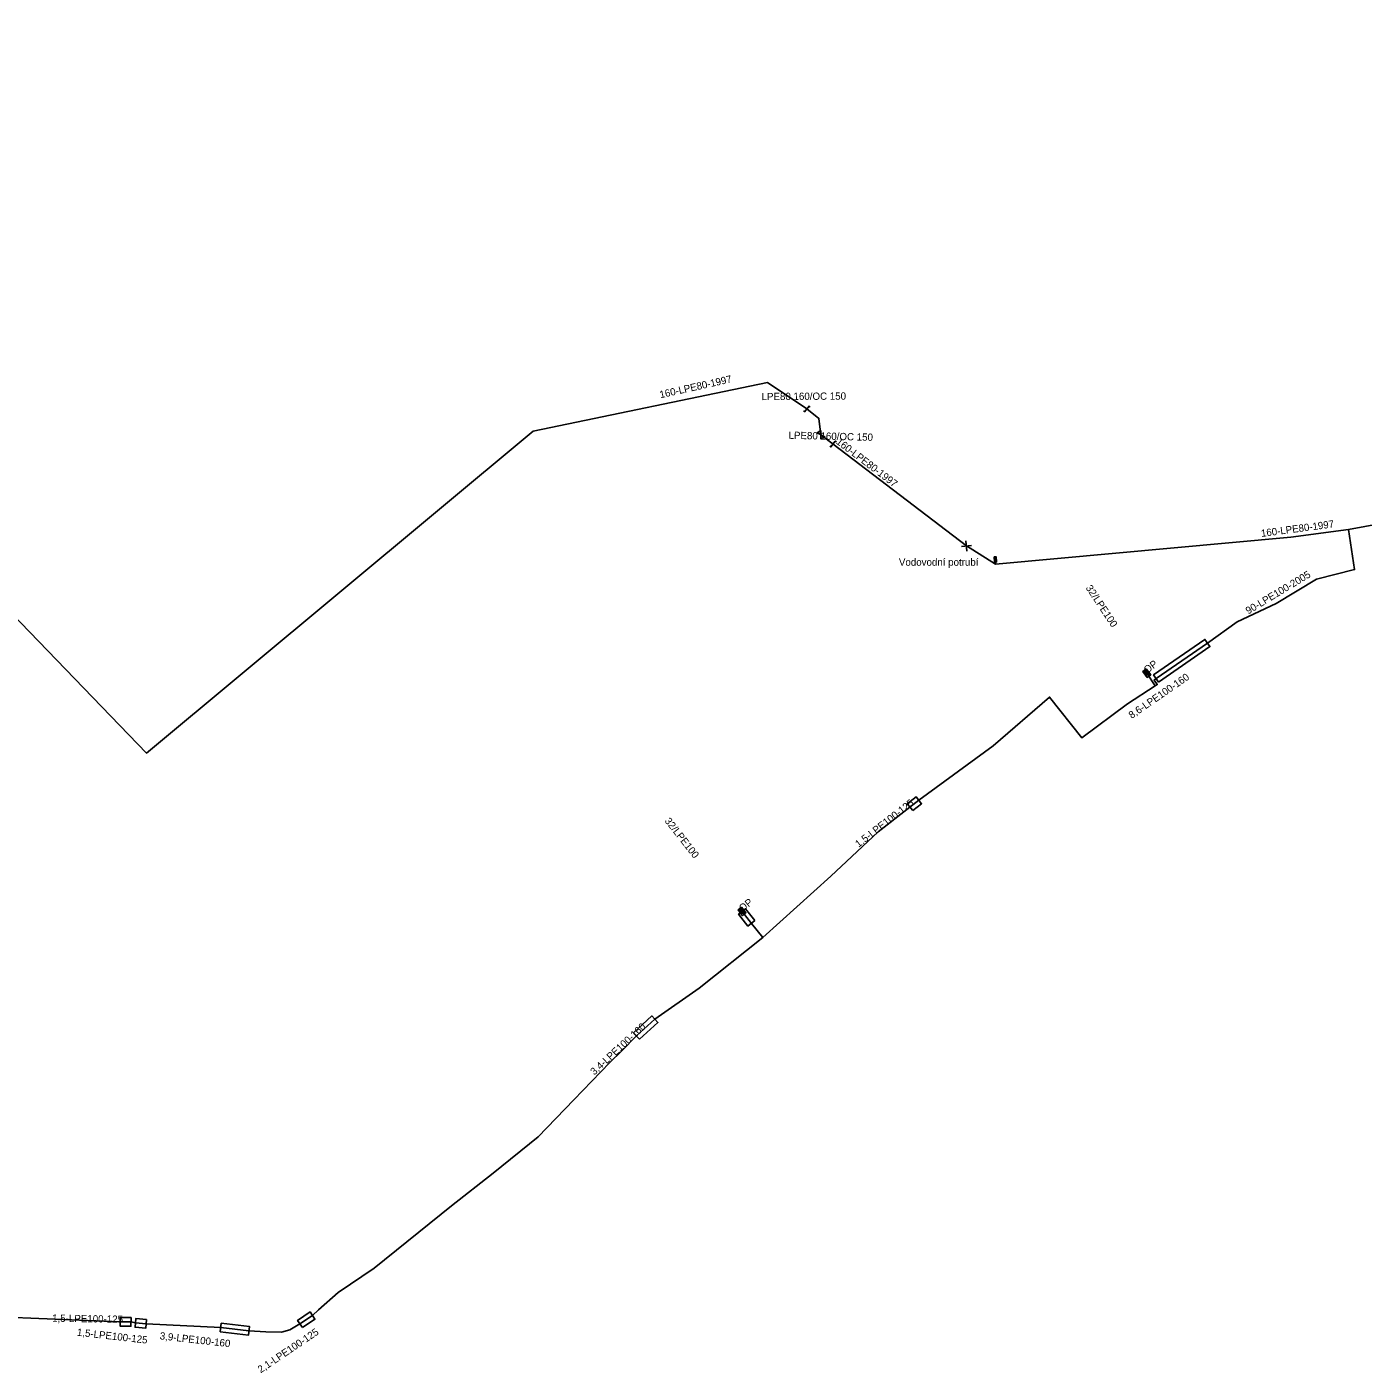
# Model space of a CAD drawing. Extents: x -762509 to -761250, y -1153000 to -1152256.
# Drawn here: x -762336.3 to -762152.8, y -1152944.2 to -1152759.4 of the extents above; entities that cross this region are included whole.
import ezdxf

# ---------------------------------------------------------------- set-up
doc = ezdxf.new("R2010")
doc.units = 0
for name, color, linetype in [('Vrstva 10', 7, 'Continuous'), ('Vrstva 21', 7, 'Continuous'), ('Vrstva 22', 7, 'Continuous'), ('Vrstva 24', 7, 'Continuous'), ('Vrstva 25', 7, 'Continuous'), ('Vrstva 29', 7, 'Continuous'), ('Vrstva 31', 7, 'Continuous'), ('Vrstva 32', 7, 'Continuous')]:
    doc.layers.add(name, color=color, linetype=linetype)

msp = doc.modelspace()

# ---------------------------------------------------------------- linework, layer by layer
at = {"layer": 'Vrstva 10'}
for p, q in [((-762207.964, -1152830.702), (-762206.557, -1152830.559)), ((-762207.189, -1152831.334), (-762207.332, -1152829.927))]:
    msp.add_line(p, q, dxfattribs=at)
at = {"layer": 'Vrstva 21'}
for points in [[(-762229.19, -1152811.83), (-762234.58, -1152808.18), (-762266.76, -1152814.86), (-762319.87, -1152859.08), (-762360.62, -1152816.89), (-762355.03, -1152811.99), (-762364.5, -1152800.75), (-762359.08, -1152772.07), (-762368.47, -1152760.2), (-762370.01, -1152761.74), (-762371.98, -1152759.36)], [(-762227.25, -1152815.36), (-762227.53, -1152813.12), (-762229.19, -1152811.83)], [(-762043.6, -1152833.45), (-762063.92, -1152811.87), (-762067.25, -1152812.52), (-762087.05, -1152815.27), (-762094.82, -1152816.92), (-762113.88, -1152820.87), (-762154.79, -1152828.37)], [(-762225.59, -1152816.64), (-762227.25, -1152815.36)], [(-762154.79, -1152828.37), (-762162.71, -1152829.42), (-762203.27, -1152833.15), (-762207.26, -1152830.63), (-762225.59, -1152816.64)], [(-762254.61, -1152899.97), (-762252.57, -1152897.94), (-762250.06, -1152895.63), (-762243.97, -1152891.38), (-762235.23, -1152884.43), (-762225.91, -1152876.01), (-762219.4, -1152869.9), (-762215.02, -1152866.52), (-762213.8, -1152865.57), (-762203.61, -1152858.08), (-762195.85, -1152851.4), (-762191.43, -1152856.97), (-762185.16, -1152852.33), (-762181.35, -1152849.84), (-762181.05, -1152849.69), (-762181.49, -1152849.07), (-762181.22, -1152848.85), (-762174.17, -1152843.97), (-762170.09, -1152841.05), (-762164.74, -1152838.54), (-762159.19, -1152835.19), (-762153.96, -1152833.88), (-762154.79, -1152828.37)], [(-762303.5, -1152938.57), (-762301.37, -1152938.63), (-762300.22, -1152938.31), (-762298.81, -1152937.49), (-762297.09, -1152936.33), (-762296.25, -1152935.55), (-762293.55, -1152933.16), (-762288.61, -1152929.82), (-762277.99, -1152921.28), (-762272.26, -1152916.76), (-762266.07, -1152911.77), (-762261.21, -1152906.72), (-762256.26, -1152901.6), (-762254.61, -1152899.97)], [(-762367.09, -1152935.51), (-762362.63, -1152935.58), (-762356.49, -1152935.86), (-762341.39, -1152936.46), (-762323.51, -1152937.19), (-762322.03, -1152937.21), (-762321.41, -1152937.33), (-762319.93, -1152937.48), (-762309.7, -1152937.99), (-762305.82, -1152938.43), (-762303.5, -1152938.57)]]:
    msp.add_lwpolyline(points, dxfattribs=at)
at = {"layer": 'Vrstva 22'}
msp.add_lwpolyline([(-762227.248, -1152814.777), (-762227.253, -1152815.943), (-762226.737, -1152815.637), (-762227.764, -1152815.083), (-762227.248, -1152814.777)], dxfattribs=at)
at = {"layer": 'Vrstva 24'}
msp.add_line((-762203.31, -1152832.151), (-762203.27, -1152833.15), dxfattribs=at)
msp.add_lwpolyline([(-762203.46, -1152832.157), (-762203.16, -1152832.145), (-762203.132, -1152832.844), (-762203.432, -1152832.856), (-762203.46, -1152832.157)], dxfattribs=at)
at = {"layer": 'Vrstva 25'}
for points in [[(-762229.659, -1152812.095), (-762229.503, -1152812.22), (-762228.877, -1152811.44), (-762228.721, -1152811.565)], [(-762226.051, -1152816.919), (-762225.891, -1152817.04), (-762225.289, -1152816.241), (-762225.129, -1152816.361)]]:
    msp.add_lwpolyline(points, dxfattribs=at)
at = {"layer": 'Vrstva 29'}
for points in [[(-762180.88, -1152849.34), (-762173.83, -1152844.46), (-762174.51, -1152843.48), (-762181.56, -1152848.36)], [(-762214.65, -1152866.99), (-762213.43, -1152866.04), (-762214.17, -1152865.1), (-762215.39, -1152866.05)], [(-762236.34, -1152882.1), (-762237.62, -1152880.47), (-762238.56, -1152881.21), (-762237.28, -1152882.84)], [(-762252.16, -1152898.38), (-762249.65, -1152896.07), (-762250.47, -1152895.19), (-762252.98, -1152897.5)], [(-762298.47, -1152937.99), (-762296.75, -1152936.83), (-762297.43, -1152935.83), (-762299.15, -1152936.99)], [(-762322.02, -1152936.61), (-762323.5, -1152936.59), (-762323.52, -1152937.79), (-762322.04, -1152937.81)], [(-762319.87, -1152936.88), (-762321.35, -1152936.73), (-762321.47, -1152937.93), (-762319.99, -1152938.08)], [(-762309.77, -1152938.59), (-762305.89, -1152939.03), (-762305.75, -1152937.83), (-762309.63, -1152937.39)]]:
    msp.add_lwpolyline(points, close=True, dxfattribs=at)
at = {"layer": 'Vrstva 31'}
for points in [[(-762181.35, -1152849.84), (-762182.5, -1152848.11)], [(-762235.23, -1152884.43), (-762236.81, -1152882.47), (-762238.09, -1152880.84)]]:
    msp.add_lwpolyline(points, dxfattribs=at)
at = {"layer": 'Vrstva 32'}
for p, q in [((-762182.603, -1152847.686), (-762182.882, -1152847.898)), ((-762182.76, -1152848.058), (-762182.481, -1152847.846)), ((-762182.734, -1152847.786), (-762182.613, -1152847.946)), ((-762182.518, -1152848.375), (-762182.239, -1152848.163)), ((-762238.199, -1152880.418), (-762238.474, -1152880.634)), ((-762238.35, -1152880.792), (-762238.075, -1152880.576)), ((-762238.329, -1152880.52), (-762238.205, -1152880.678)), ((-762238.104, -1152881.106), (-762237.828, -1152880.89))]:
    msp.add_line(p, q, dxfattribs=at)
for points in [[(-762182.564, -1152847.53), (-762181.958, -1152848.326), (-762182.435, -1152848.689), (-762183.042, -1152847.894), (-762182.564, -1152847.53)], [(-762182.421, -1152847.924), (-762182.621, -1152848.076), (-762182.651, -1152848.117), (-762182.659, -1152848.162), (-762182.647, -1152848.206), (-762182.629, -1152848.229), (-762182.59, -1152848.252), (-762182.547, -1152848.255), (-762182.499, -1152848.236), (-762182.299, -1152848.084)], [(-762182.239, -1152848.163), (-762182.161, -1152848.266), (-762182.149, -1152848.31), (-762182.152, -1152848.332), (-762182.17, -1152848.363), (-762182.21, -1152848.393), (-762182.245, -1152848.402), (-762182.266, -1152848.4), (-762182.305, -1152848.377), (-762182.384, -1152848.273)], [(-762238.162, -1152880.262), (-762237.545, -1152881.048), (-762238.017, -1152881.419), (-762238.634, -1152880.632), (-762238.162, -1152880.262)], [(-762238.014, -1152880.654), (-762238.211, -1152880.809), (-762238.241, -1152880.85), (-762238.248, -1152880.895), (-762238.235, -1152880.938), (-762238.217, -1152880.961), (-762238.178, -1152880.983), (-762238.134, -1152880.986), (-762238.087, -1152880.967), (-762237.889, -1152880.812)], [(-762237.828, -1152880.89), (-762237.748, -1152880.992), (-762237.735, -1152881.035), (-762237.739, -1152881.057), (-762237.756, -1152881.088), (-762237.795, -1152881.119), (-762237.83, -1152881.129), (-762237.852, -1152881.127), (-762237.891, -1152881.104), (-762237.971, -1152881.002)]]:
    msp.add_lwpolyline(points, dxfattribs=at)

# ---------------------------------------------------------------- texts
at = {"layer": 'Vrstva 10'}
msp.add_text('Vodovodní potrubí', height=1, dxfattribs=at).set_placement((-762216.54, -1152833.36))
at = {"layer": 'Vrstva 21'}
for s, rotation, p in [('160-LPE80-1997', 12.57108, (-762249.3, -1152810.36)), ('160-LPE80-1997', 322.64805, (-762225.25, -1152816.51)), ('160-LPE80-1997', 7.55209, (-762166.74, -1152829.41)), ('90-LPE100-2005', 31.11533, (-762168.54, -1152840.06))]:
    msp.add_text(s, height=1, rotation=rotation, dxfattribs=at).set_placement(p)
at = {"layer": 'Vrstva 25'}
for rotation, p in [(0.36011, (-762235.4, -1152810.62)), (358.54173, (-762231.71, -1152815.92))]:
    msp.add_text('LPE80 160/OC 150', height=1, rotation=rotation, dxfattribs=at).set_placement(p)
at = {"layer": 'Vrstva 29'}
for s, rotation, p in [('8,6-LPE100-160', 34.69093, (-762184.56, -1152854.41)), ('1,5-LPE100-125', 37.90748, (-762222.08, -1152872.1)), ('3,4-LPE100-160', 42.62394, (-762258.38, -1152903.38)), ('1,5-LPE100-125', 359.03823, (-762332.86, -1152937.18)), ('1,5-LPE100-125', 353.50542, (-762329.49, -1152939.09)), ('2,1-LPE100-125', 33.99646, (-762304.2, -1152944.27)), ('3,9-LPE100-160', 353.53018, (-762318.11, -1152939.59))]:
    msp.add_text(s, height=1, rotation=rotation, dxfattribs=at).set_placement(p)
at = {"layer": 'Vrstva 31'}
for rotation, p in [(303.61357, (-762190.93, -1152836.4)), (303.61357, (-762190.93, -1152836.4)), (308.1417, (-762248.78, -1152868.43)), (308.1417, (-762248.78, -1152868.43))]:
    msp.add_text('32/LPE100', height=1, rotation=rotation, dxfattribs=at).set_placement(p)
at = {"layer": 'Vrstva 32'}
for rotation, p in [(37.31075, (-762182.44, -1152848.2)), (37.31075, (-762182.44, -1152848.2)), (38.1417, (-762238.03, -1152880.94)), (38.1417, (-762238.03, -1152880.94))]:
    msp.add_text('OP', height=1, rotation=rotation, dxfattribs=at).set_placement(p)

doc.saveas('drawing.dxf')
